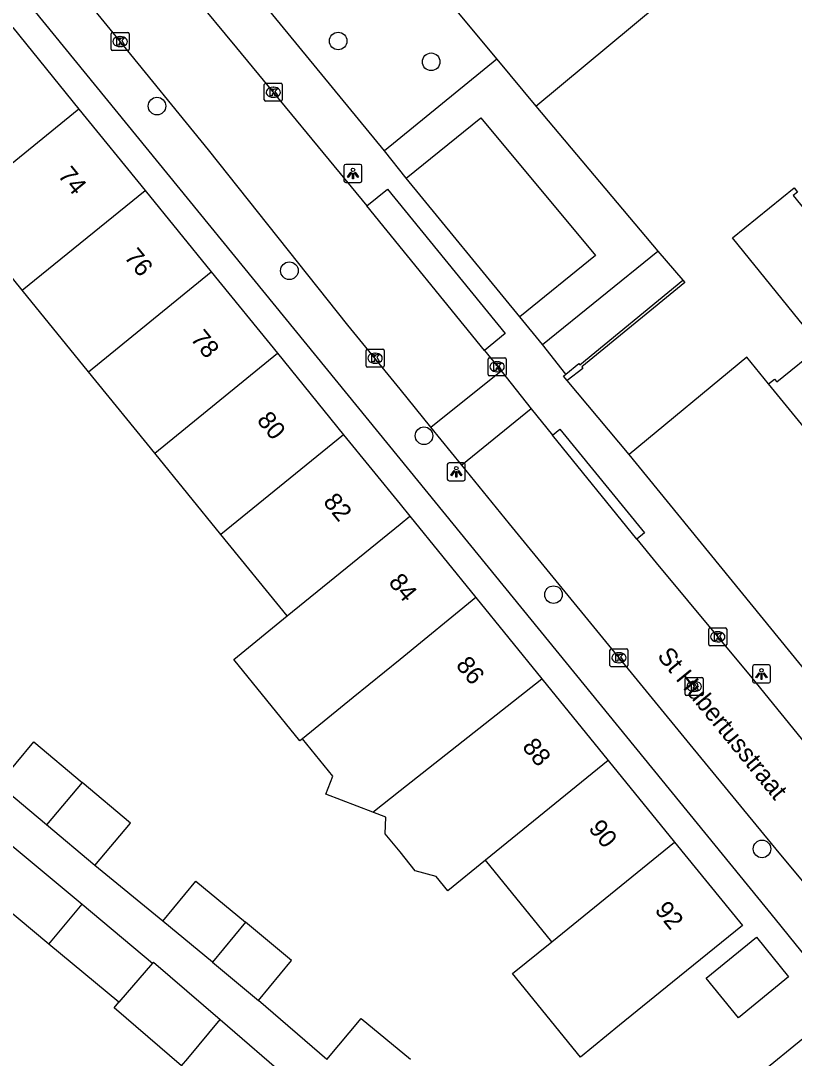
# Model space of a CAD drawing. Extents: x 162074 to 163034, y 381824 to 382557.
# Drawn here: x 162478.9 to 162521.9, y 381883.6 to 381941.3 of the extents above; entities that cross this region are included whole.
import ezdxf

# ---------------------------------------------------------------- set-up
doc = ezdxf.new("R2010")
doc.units = 0
for name, color, linetype in [('IMGEO_Boom', 7, 'Continuous'), ('IMGEO_Groenvoorziening', 7, 'Continuous'), ('IMGEO_Kolk', 7, 'Continuous'), ('IMGEO_Lichtpunt', 7, 'Continuous'), ('IMGEO_Muur', 7, 'Continuous'), ('IMGEO_Openbare_ruimte_label', 7, 'Continuous'), ('IMGEO_Pand', 7, 'Continuous'), ('IMGEO_Pand_nummerreeks', 7, 'Continuous'), ('IMGEO_Parkeervlak_open', 7, 'Continuous'), ('IMGEO_Rijbaan_lokaal_open', 7, 'Continuous'), ('IMGEO_Rioolput', 7, 'Continuous'), ('IMGEO_Voetpad_open', 7, 'Continuous')]:
    doc.layers.add(name, color=color, linetype=linetype)

msp = doc.modelspace()

# ---------------------------------------------------------------- linework, layer by layer
at = {"layer": 'IMGEO_Boom'}
for centre in [(162496.56, 381940.166), (162501.732, 381939.011), (162486.484, 381936.547), (162493.848, 381927.391), (162501.333, 381918.213), (162508.537, 381909.378), (162520.133, 381895.236)]:
    msp.add_circle(centre, 0.489, dxfattribs=at)
at = {"layer": 'IMGEO_Groenvoorziening'}
msp.add_lwpolyline([(162514.34, 381928.488), (162515.721, 381926.862)], dxfattribs=at)
at = {"layer": 'IMGEO_Kolk'}
for p, q in [((162483.935, 381939.711), (162483.935, 381940.563)), ((162484.01, 381940.637), (162484.862, 381940.637)), ((162484.423, 381940.417), (162484.448, 381940.417)), ((162484.936, 381940.563), (162484.936, 381939.711)), ((162484.446, 381939.857), (162484.421, 381939.857)), ((162484.862, 381939.637), (162484.01, 381939.637)), ((162492.452, 381936.888), (162492.452, 381937.74)), ((162492.527, 381937.814), (162493.379, 381937.814)), ((162492.94, 381937.594), (162492.965, 381937.594)), ((162493.453, 381937.74), (162493.453, 381936.888)), ((162492.963, 381937.034), (162492.938, 381937.034)), ((162493.379, 381936.814), (162492.527, 381936.814)), ((162498.114, 381922.1), (162498.114, 381922.952)), ((162498.189, 381923.026), (162499.041, 381923.026)), ((162498.602, 381922.806), (162498.627, 381922.806)), ((162499.115, 381922.952), (162499.115, 381922.1)), ((162504.899, 381921.625), (162504.899, 381922.477)), ((162504.974, 381922.551), (162505.826, 381922.551)), ((162505.9, 381922.477), (162505.9, 381921.625)), ((162499.041, 381922.026), (162498.189, 381922.026)), ((162498.625, 381922.246), (162498.6, 381922.246)), ((162505.387, 381922.331), (162505.412, 381922.331)), ((162505.826, 381921.551), (162504.974, 381921.551)), ((162505.41, 381921.771), (162505.385, 381921.771)), ((162517.242, 381907.532), (162518.094, 381907.532)), ((162517.167, 381906.606), (162517.167, 381907.458)), ((162517.655, 381907.312), (162517.68, 381907.312)), ((162518.168, 381907.458), (162518.168, 381906.606)), ((162511.751, 381906.369), (162512.603, 381906.369)), ((162518.094, 381906.532), (162517.242, 381906.532)), ((162517.678, 381906.752), (162517.653, 381906.752)), ((162511.676, 381905.443), (162511.676, 381906.295)), ((162512.164, 381906.149), (162512.189, 381906.149)), ((162512.677, 381906.295), (162512.677, 381905.443)), ((162512.603, 381905.369), (162511.751, 381905.369)), ((162512.187, 381905.589), (162512.162, 381905.589))]:
    msp.add_line(p, q, dxfattribs=at)
for points in [[(162483.935, 381939.711), (162483.935, 381940.563)], [(162484.01, 381940.637), (162484.862, 381940.637)], [(162484.936, 381940.563), (162484.936, 381939.711)], [(162484.256, 381940.337), (162484.379, 381940.337), (162484.379, 381940.186), (162484.509, 381940.337), (162484.673, 381940.337), (162484.527, 381940.186), (162484.68, 381939.937), (162484.528, 381939.937), (162484.443, 381940.101), (162484.379, 381940.034), (162484.379, 381939.937), (162484.256, 381939.937), (162484.256, 381940.337)], [(162484.862, 381939.637), (162484.01, 381939.637)], [(162492.452, 381936.888), (162492.452, 381937.74)], [(162492.527, 381937.814), (162493.379, 381937.814)], [(162492.773, 381937.514), (162492.896, 381937.514), (162492.896, 381937.363), (162493.026, 381937.514), (162493.19, 381937.514), (162493.044, 381937.363), (162493.197, 381937.114), (162493.045, 381937.114), (162492.96, 381937.278), (162492.896, 381937.211), (162492.896, 381937.114), (162492.773, 381937.114), (162492.773, 381937.514)], [(162493.453, 381937.74), (162493.453, 381936.888)], [(162493.379, 381936.814), (162492.527, 381936.814)], [(162498.114, 381922.1), (162498.114, 381922.952)], [(162498.189, 381923.026), (162499.041, 381923.026)], [(162498.435, 381922.726), (162498.558, 381922.726), (162498.558, 381922.575), (162498.688, 381922.726), (162498.852, 381922.726), (162498.706, 381922.575), (162498.859, 381922.326), (162498.707, 381922.326), (162498.622, 381922.49), (162498.558, 381922.423), (162498.558, 381922.326), (162498.435, 381922.326), (162498.435, 381922.726)], [(162499.115, 381922.952), (162499.115, 381922.1)], [(162504.899, 381921.625), (162504.899, 381922.477)], [(162504.974, 381922.551), (162505.826, 381922.551)], [(162505.9, 381922.477), (162505.9, 381921.625)], [(162499.041, 381922.026), (162498.189, 381922.026)], [(162505.22, 381922.251), (162505.343, 381922.251), (162505.343, 381922.1), (162505.473, 381922.251), (162505.637, 381922.251), (162505.491, 381922.1), (162505.644, 381921.851), (162505.492, 381921.851), (162505.407, 381922.015), (162505.343, 381921.948), (162505.343, 381921.851), (162505.22, 381921.851), (162505.22, 381922.251)], [(162505.826, 381921.551), (162504.974, 381921.551)], [(162517.242, 381907.532), (162518.094, 381907.532)], [(162517.167, 381906.606), (162517.167, 381907.458)], [(162517.488, 381907.232), (162517.611, 381907.232), (162517.611, 381907.081), (162517.741, 381907.232), (162517.905, 381907.232), (162517.759, 381907.081), (162517.912, 381906.832), (162517.76, 381906.832), (162517.675, 381906.996), (162517.611, 381906.929), (162517.611, 381906.832), (162517.488, 381906.832), (162517.488, 381907.232)], [(162518.168, 381907.458), (162518.168, 381906.606)], [(162511.751, 381906.369), (162512.603, 381906.369)], [(162518.094, 381906.532), (162517.242, 381906.532)], [(162511.676, 381905.443), (162511.676, 381906.295)], [(162511.997, 381906.069), (162512.12, 381906.069), (162512.12, 381905.918), (162512.25, 381906.069), (162512.414, 381906.069), (162512.268, 381905.918), (162512.421, 381905.669), (162512.269, 381905.669), (162512.184, 381905.833), (162512.12, 381905.766), (162512.12, 381905.669), (162511.997, 381905.669), (162511.997, 381906.069)], [(162512.677, 381906.295), (162512.677, 381905.443)], [(162512.603, 381905.369), (162511.751, 381905.369)]]:
    msp.add_lwpolyline(points, dxfattribs=at)
for centre, start, end in [((162484.012, 381940.561), 91.55205, 178.44795), ((162484.012, 381940.561), 91.55205, 178.44795), ((162484.86, 381940.561), 1.55205, 88.44795), ((162484.86, 381940.561), 1.55205, 88.44795), ((162484.012, 381939.713), 181.55205, 268.44795), ((162484.012, 381939.713), 181.55205, 268.44795), ((162484.86, 381939.713), 271.55205, 358.44795), ((162484.86, 381939.713), 271.55205, 358.44795), ((162492.529, 381937.738), 91.55205, 178.44795), ((162492.529, 381937.738), 91.55205, 178.44795), ((162493.377, 381937.738), 1.55205, 88.44795), ((162493.377, 381937.738), 1.55205, 88.44795), ((162492.529, 381936.89), 181.55205, 268.44795), ((162492.529, 381936.89), 181.55205, 268.44795), ((162493.377, 381936.89), 271.55205, 358.44795), ((162493.377, 381936.89), 271.55205, 358.44795), ((162498.191, 381922.95), 91.55205, 178.44795), ((162498.191, 381922.95), 91.55205, 178.44795), ((162499.039, 381922.95), 1.55205, 88.44795), ((162499.039, 381922.95), 1.55205, 88.44795), ((162504.976, 381922.475), 91.55205, 178.44795), ((162504.976, 381922.475), 91.55205, 178.44795), ((162505.824, 381922.475), 1.55205, 88.44795), ((162505.824, 381922.475), 1.55205, 88.44795), ((162498.191, 381922.102), 181.55205, 268.44795), ((162498.191, 381922.102), 181.55205, 268.44795), ((162499.039, 381922.102), 271.55205, 358.44795), ((162499.039, 381922.102), 271.55205, 358.44795), ((162504.976, 381921.627), 181.55205, 268.44795), ((162504.976, 381921.627), 181.55205, 268.44795), ((162505.824, 381921.627), 271.55205, 358.44795), ((162505.824, 381921.627), 271.55205, 358.44795), ((162517.244, 381907.456), 91.55205, 178.44795), ((162517.244, 381907.456), 91.55205, 178.44795), ((162518.092, 381907.456), 1.55205, 88.44795), ((162518.092, 381907.456), 1.55205, 88.44795), ((162511.753, 381906.293), 91.55205, 178.44795), ((162511.753, 381906.293), 91.55205, 178.44795), ((162512.601, 381906.293), 1.55205, 88.44795), ((162512.601, 381906.293), 1.55205, 88.44795), ((162517.244, 381906.608), 181.55205, 268.44795), ((162517.244, 381906.608), 181.55205, 268.44795), ((162518.092, 381906.608), 271.55205, 358.44795), ((162518.092, 381906.608), 271.55205, 358.44795), ((162511.753, 381905.445), 181.55205, 268.44795), ((162511.753, 381905.445), 181.55205, 268.44795), ((162512.601, 381905.445), 271.55205, 358.44795), ((162512.601, 381905.445), 271.55205, 358.44795)]:
    msp.add_arc(centre, 0.0765, start, end, dxfattribs=at)
for centre, major_axis, ratio, start_param, end_param in [((162484.422, 381940.137), (-0.387, 0.002), 0.722429, 4.712389, 7.853982), ((162484.447, 381940.137), (-0.39, 0.002), 0.717154, 1.570796, 4.712389), ((162492.939, 381937.314), (-0.387, 0.002), 0.722429, 4.712389, 7.853982), ((162492.964, 381937.314), (-0.39, 0.002), 0.717154, 1.570796, 4.712389), ((162498.601, 381922.526), (-0.387, 0.002), 0.722429, 4.712389, 7.853982), ((162498.626, 381922.526), (-0.39, 0.002), 0.717154, 1.570796, 4.712389), ((162505.386, 381922.051), (-0.387, 0.002), 0.722429, 4.712389, 7.853982), ((162505.411, 381922.051), (-0.39, 0.002), 0.717154, 1.570796, 4.712389), ((162517.654, 381907.032), (-0.387, 0.002), 0.722429, 4.712389, 7.853982), ((162517.679, 381907.032), (-0.39, 0.002), 0.717154, 1.570796, 4.712389), ((162512.163, 381905.869), (-0.387, 0.002), 0.722429, 4.712389, 7.853982), ((162512.188, 381905.869), (-0.39, 0.002), 0.717154, 1.570796, 4.712389)]:
    msp.add_ellipse(centre, major_axis=major_axis, ratio=ratio, start_param=start_param, end_param=end_param, dxfattribs=at)
at = {"layer": 'IMGEO_Lichtpunt'}
for p, q in [((162496.883, 381933.206), (162496.883, 381932.399)), ((162496.883, 381933.206), (162496.883, 381932.399)), ((162497.785, 381933.301), (162496.977, 381933.301)), ((162497.785, 381933.301), (162496.977, 381933.301)), ((162497.879, 381932.399), (162497.879, 381933.206)), ((162497.879, 381932.399), (162497.879, 381933.206)), ((162496.977, 381932.305), (162497.785, 381932.305)), ((162496.977, 381932.305), (162497.785, 381932.305)), ((162503.532, 381916.707), (162502.724, 381916.707)), ((162503.532, 381916.707), (162502.724, 381916.707)), ((162502.63, 381916.612), (162502.63, 381915.805)), ((162502.63, 381916.612), (162502.63, 381915.805)), ((162503.626, 381915.805), (162503.626, 381916.612)), ((162503.626, 381915.805), (162503.626, 381916.612)), ((162502.724, 381915.711), (162503.532, 381915.711)), ((162502.724, 381915.711), (162503.532, 381915.711)), ((162519.604, 381905.371), (162519.604, 381904.564)), ((162519.604, 381905.371), (162519.604, 381904.564)), ((162520.506, 381905.466), (162519.698, 381905.466)), ((162520.506, 381905.466), (162519.698, 381905.466)), ((162520.6, 381904.564), (162520.6, 381905.371)), ((162520.6, 381904.564), (162520.6, 381905.371)), ((162519.698, 381904.47), (162520.506, 381904.47)), ((162519.698, 381904.47), (162520.506, 381904.47))]:
    msp.add_line(p, q, dxfattribs=at)
for points in [[(162497.257, 381932.87), (162497.296, 381932.842), (162497.108, 381932.58), (162497.07, 381932.607), (162497.257, 381932.87)], [(162497.469, 381932.842), (162497.507, 381932.869), (162497.694, 381932.607), (162497.655, 381932.579), (162497.469, 381932.842)], [(162497.359, 381932.822), (162497.406, 381932.822), (162497.406, 381932.5), (162497.359, 381932.5), (162497.359, 381932.822)], [(162503.004, 381916.276), (162503.043, 381916.248), (162502.855, 381915.986), (162502.817, 381916.013), (162503.004, 381916.276)], [(162503.106, 381916.228), (162503.153, 381916.228), (162503.153, 381915.906), (162503.106, 381915.906), (162503.106, 381916.228)], [(162503.216, 381916.248), (162503.254, 381916.275), (162503.441, 381916.013), (162503.402, 381915.985), (162503.216, 381916.248)], [(162519.978, 381905.035), (162520.017, 381905.007), (162519.829, 381904.745), (162519.791, 381904.772), (162519.978, 381905.035)], [(162520.08, 381904.987), (162520.127, 381904.987), (162520.127, 381904.665), (162520.08, 381904.665), (162520.08, 381904.987)], [(162520.19, 381905.007), (162520.228, 381905.034), (162520.415, 381904.772), (162520.376, 381904.744), (162520.19, 381905.007)]]:
    msp.add_lwpolyline(points, dxfattribs=at)
for centre in [(162497.382, 381933.004), (162503.129, 381916.41), (162520.103, 381905.169)]:
    msp.add_circle(centre, 0.0994, dxfattribs=at)
for centre, start, end in [((162496.977, 381933.206), 90, 180), ((162496.977, 381933.206), 90, 180), ((162497.785, 381933.206), 0, 90), ((162497.785, 381933.206), 0, 90), ((162496.977, 381932.399), 180, 270), ((162496.977, 381932.399), 180, 270), ((162497.785, 381932.399), 270, 0), ((162497.785, 381932.399), 270, 360), ((162502.724, 381916.612), 90, 180), ((162502.724, 381916.612), 90, 180), ((162503.532, 381916.612), 0, 90), ((162503.532, 381916.612), 0, 90), ((162502.724, 381915.805), 180, 270), ((162502.724, 381915.805), 180, 270), ((162503.532, 381915.805), 270, 0), ((162503.532, 381915.805), 270, 360), ((162519.698, 381905.371), 90, 180), ((162519.698, 381905.371), 90, 180), ((162520.506, 381905.371), 0, 90), ((162520.506, 381905.371), 0, 90), ((162519.698, 381904.564), 180, 270), ((162519.698, 381904.564), 180, 270), ((162520.506, 381904.564), 270, 0), ((162520.506, 381904.564), 270, 360)]:
    msp.add_arc(centre, 0.0946, start, end, dxfattribs=at)
at = {"layer": 'IMGEO_Muur'}
for points in [[(162507.558, 381936.537), (162514.34, 381928.488)], [(162514.34, 381928.488), (162515.721, 381926.862)], [(162509.219, 381921.638), (162509.944, 381922.228), (162510.007, 381922.15), (162515.721, 381926.862)], [(162515.721, 381926.862), (162515.832, 381926.732), (162510.103, 381922.04), (162510.164, 381921.961), (162509.295, 381921.293)], [(162509.295, 381921.293), (162509.093, 381921.535), (162509.219, 381921.638)]]:
    msp.add_lwpolyline(points, dxfattribs=at)
at = {"layer": 'IMGEO_Pand'}
for points in [[(162528.039, 381971.287), (162498.859, 381947.001), (162505.384, 381939.152)], [(162507.558, 381936.537), (162534.655, 381959.09), (162538.114, 381954.837), (162542.837, 381949.03)], [(162520.5, 381921.098), (162520.833, 381921.369), (162520.965, 381921.205), (162523.392, 381923.18), (162518.484, 381929.214), (162521.92, 381932.008), (162522.115, 381931.767), (162521.874, 381931.571), (162523.331, 381929.779), (162542.062, 381945.012), (162540.598, 381946.811), (162540.505, 381946.734), (162540.309, 381946.974), (162542.837, 381949.03)], [(162478.463, 381940.914), (162482.143, 381936.385)], [(162505.384, 381939.152), (162507.558, 381936.537)], [(162482.143, 381936.385), (162475.314, 381930.836)], [(162482.143, 381936.385), (162485.824, 381931.855)], [(162478.994, 381926.306), (162485.824, 381931.855)], [(162485.824, 381931.855), (162489.503, 381927.327)], [(162478.994, 381926.306), (162475.314, 381930.836)], [(162482.674, 381921.777), (162489.503, 381927.327)], [(162489.503, 381927.327), (162493.184, 381922.797)], [(162482.674, 381921.777), (162478.994, 381926.306)], [(162486.355, 381917.247), (162493.184, 381922.797)], [(162493.184, 381922.797), (162496.864, 381918.268)], [(162486.355, 381917.247), (162482.674, 381921.777)], [(162574.906, 381913.476), (162548.915, 381892.214), (162544.533, 381897.571), (162540.51, 381894.28), (162536.692, 381898.947), (162537.847, 381899.893), (162520.5, 381921.098)], [(162496.864, 381918.268), (162490.035, 381912.718)], [(162496.864, 381918.268), (162500, 381914.408), (162500.545, 381913.738)], [(162490.035, 381912.718), (162486.355, 381917.247)], [(162493.715, 381908.189), (162500, 381913.295), (162500.545, 381913.738)], [(162500.545, 381913.738), (162504.224, 381909.209)], [(162493.715, 381908.189), (162490.035, 381912.718)], [(162504.224, 381909.209), (162500, 381905.778), (162497.394, 381903.661), (162494.568, 381901.366)], [(162504.224, 381909.209), (162507.89, 381904.698)], [(162494.568, 381901.366), (162494.427, 381901.251), (162490.748, 381905.778), (162493.715, 381908.189)], [(162498.48, 381897.283), (162500, 381898.48), (162507.89, 381904.698)], [(162507.89, 381904.698), (162511.585, 381900.15)], [(162477.652, 381898.823), (162479.636, 381901.183), (162482.32, 381898.926)], [(162498.48, 381897.283), (162495.87, 381898.273), (162496.255, 381899.289), (162494.568, 381901.366)], [(162511.585, 381900.15), (162504.756, 381894.601)], [(162511.585, 381900.15), (162515.265, 381895.62)], [(162480.335, 381896.566), (162477.652, 381898.823)], [(162482.32, 381898.926), (162480.335, 381896.566)], [(162483.019, 381894.309), (162485.004, 381896.669), (162482.32, 381898.926)], [(162504.756, 381894.601), (162502.651, 381892.908), (162502.003, 381893.706), (162500.845, 381894.024), (162500, 381895.064), (162499.175, 381896.08), (162499.212, 381897.006), (162498.48, 381897.283)], [(162483.019, 381894.309), (162480.335, 381896.566)], [(162477.982, 381895.771), (162482.321, 381892.159)], [(162515.265, 381895.62), (162519.04, 381890.974), (162515.16, 381887.822), (162512.211, 381885.426), (162510.029, 381883.653), (162506.254, 381888.3), (162508.436, 381890.072)], [(162508.436, 381890.072), (162515.265, 381895.62)], [(162508.436, 381890.072), (162504.756, 381894.601)], [(162480.473, 381889.94), (162476.133, 381893.553)], [(162486.809, 381891.223), (162488.652, 381893.446), (162491.415, 381891.153)], [(162480.473, 381889.94), (162482.321, 381892.159)], [(162482.321, 381892.159), (162486.242, 381888.884)], [(162489.572, 381888.931), (162486.809, 381891.223)], [(162491.415, 381891.153), (162489.572, 381888.931)], [(162492.127, 381886.812), (162493.971, 381889.034), (162491.415, 381891.153)], [(162517.025, 381888.056), (162519.817, 381890.324), (162521.61, 381888.118), (162518.818, 381885.85), (162517.025, 381888.056)], [(162484.361, 381886.706), (162480.473, 381889.94)], [(162486.242, 381888.884), (162484.361, 381886.706)], [(162486.242, 381888.884), (162486.295, 381888.945), (162489.997, 381885.745)], [(162489.572, 381888.931), (162492.127, 381886.812)], [(162487.849, 381883.168), (162484.101, 381886.406), (162484.361, 381886.706)], [(162526.815, 381884.036), (162522.167, 381880.242), (162520.08, 381882.798), (162524.728, 381886.592)], [(162487.849, 381883.168), (162488.192, 381883.579), (162489.997, 381885.745)], [(162489.997, 381885.745), (162493.946, 381882.334), (162493.893, 381882.273)], [(162495.937, 381883.52), (162497.838, 381885.812), (162500.584, 381883.534)]]:
    msp.add_lwpolyline(points, dxfattribs=at)
at = {"layer": 'IMGEO_Parkeervlak_open'}
msp.add_lwpolyline([(162520.5, 381921.098), (162519.284, 381922.585), (162512.749, 381917.178)], dxfattribs=at)
at = {"layer": 'IMGEO_Rijbaan_lokaal_open'}
for points in [[(162483.625, 381948.585), (162490.911, 381939.795), (162498.159, 381930.991)], [(162501.711, 381918.696), (162500, 381920.802), (162497.104, 381924.368), (162489.346, 381934.115), (162484.214, 381940.41), (162482.13, 381942.984)], [(162504.696, 381922.955), (162498.159, 381930.991)], [(162504.696, 381922.955), (162505.623, 381921.819)], [(162501.711, 381918.696), (162505.623, 381921.819)], [(162505.623, 381921.819), (162507.291, 381919.708)], [(162507.291, 381919.708), (162503.432, 381916.577)], [(162507.291, 381919.708), (162508.478, 381918.241)], [(162503.432, 381916.577), (162501.711, 381918.696)], [(162513.176, 381912.467), (162508.478, 381918.241)], [(162526.59, 381888.392), (162520.92, 381895.221), (162516.305, 381900.831), (162506.083, 381913.313), (162503.432, 381916.577)], [(162513.176, 381912.467), (162514.252, 381911.144), (162519.563, 381904.75), (162529.722, 381892.262), (162534.39, 381886.566)]]:
    msp.add_lwpolyline(points, dxfattribs=at)
at = {"layer": 'IMGEO_Rioolput'}
for p, q in [((162515.863, 381903.844), (162515.863, 381904.696)), ((162515.938, 381904.77), (162516.79, 381904.77)), ((162516.864, 381904.696), (162516.864, 381903.844)), ((162516.351, 381904.55), (162516.376, 381904.55)), ((162516.79, 381903.77), (162515.938, 381903.77)), ((162516.374, 381903.99), (162516.349, 381903.99))]:
    msp.add_line(p, q, dxfattribs=at)
for points in [[(162515.863, 381903.844), (162515.863, 381904.696)], [(162515.938, 381904.77), (162516.79, 381904.77)], [(162516.864, 381904.696), (162516.864, 381903.844)], [(162516.452, 381904.468), (162516.2, 381904.47), (162516.2, 381904.07)], [(162516.2, 381904.07), (162516.324, 381904.07), (162516.324, 381904.232), (162516.335, 381904.232)], [(162516.378, 381904.389), (162516.324, 381904.389), (162516.324, 381904.308)], [(162516.324, 381904.308), (162516.376, 381904.308)], [(162516.382, 381904.203), (162516.453, 381904.07), (162516.593, 381904.07), (162516.528, 381904.196)], [(162516.79, 381903.77), (162515.938, 381903.77)]]:
    msp.add_lwpolyline(points, dxfattribs=at)
for centre, radius, start, end in [((162515.94, 381904.694), 0.0765, 91.55205, 178.44795), ((162515.94, 381904.694), 0.0765, 91.55205, 178.44795), ((162516.788, 381904.694), 0.0765, 1.55205, 88.44795), ((162516.788, 381904.694), 0.0765, 1.55205, 88.44795), ((162516.334, 381904.179), 0.0533, 26.02933, 88.69889), ((162516.36, 381904.497), 0.19, 274.7715, 282.96867), ((162516.384, 381904.293), 0.0964, 77.00612, 93.18647), ((162516.398, 381904.35), 0.0378, 276.66336, 79.67722), ((162516.451, 381904.358), 0.109, 350.36119, 89.41601), ((162516.449, 381904.358), 0.112, 277.58423, 350.98172), ((162516.433, 381904.143), 0.108, 29.51342, 73.79051), ((162515.94, 381903.846), 0.0765, 181.55205, 268.44795), ((162515.94, 381903.846), 0.0765, 181.55205, 268.44795), ((162516.788, 381903.846), 0.0765, 271.55205, 358.44795), ((162516.788, 381903.846), 0.0765, 271.55205, 358.44795)]:
    msp.add_arc(centre, radius, start, end, dxfattribs=at)
for centre, major_axis, ratio, start_param, end_param in [((162516.35, 381904.27), (-0.387, 0.002), 0.722429, 4.712389, 7.853982), ((162516.375, 381904.27), (-0.39, 0.002), 0.717154, 1.570796, 4.712389)]:
    msp.add_ellipse(centre, major_axis=major_axis, ratio=ratio, start_param=start_param, end_param=end_param, dxfattribs=at)
at = {"layer": 'IMGEO_Voetpad_open'}
for points in [[(162524.728, 381886.592), (162523.779, 381887.754), (162520.879, 381891.323), (162500, 381916.926), (162479.554, 381941.998), (162475.997, 381945.948)], [(162499.145, 381934.054), (162491.482, 381943.405)], [(162505.384, 381939.152), (162499.145, 381934.054)], [(162507.558, 381936.537), (162514.34, 381928.488)], [(162500.349, 381932.535), (162504.486, 381935.898), (162510.875, 381928.232), (162506.656, 381924.819)], [(162500.349, 381932.535), (162499.145, 381934.054)], [(162506.656, 381924.819), (162500.349, 381932.535)], [(162498.159, 381930.991), (162499.303, 381931.936), (162505.851, 381923.894), (162504.696, 381922.955)], [(162507.92, 381923.28), (162514.34, 381928.488)], [(162507.92, 381923.28), (162506.656, 381924.819)], [(162509.219, 381921.638), (162507.92, 381923.28)], [(162512.749, 381917.178), (162509.295, 381921.293)], [(162508.478, 381918.241), (162508.885, 381918.573), (162513.594, 381912.808), (162513.176, 381912.467)], [(162536.387, 381888.203), (162512.749, 381917.178)], [(162486.809, 381891.223), (162483.019, 381894.309)], [(162495.937, 381883.52), (162492.127, 381886.812)]]:
    msp.add_lwpolyline(points, dxfattribs=at)

# ---------------------------------------------------------------- texts
at = {"layer": 'IMGEO_Openbare_ruimte_label'}
msp.add_text('St Hubertusstraat', height=1, rotation=309.27731, dxfattribs=at).set_placement((162514.265, 381905.944))
at = {"layer": 'IMGEO_Pand_nummerreeks'}
for s, rotation, p in [('74', 309.09422, (162480.93, 381932.677)), ('76', 309.09422, (162484.618, 381928.137)), ('78', 309.09422, (162488.309, 381923.595)), ('80', 309.09422, (162491.998, 381919.055)), ('82', 309.09422, (162495.683, 381914.519)), ('84', 309.08697, (162499.318, 381910.048)), ('86', 309.09422, (162503.062, 381905.437)), ('88', 309.09422, (162506.753, 381900.895)), ('90', 309.09422, (162510.442, 381896.355)), ('92', 309.0927, (162514.126, 381891.818))]:
    msp.add_text(s, height=1, rotation=rotation, dxfattribs=at).set_placement(p)

doc.saveas('drawing.dxf')
